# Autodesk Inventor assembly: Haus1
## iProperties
Shininess: 64.0
Length Units: 11269
Angle Units: 11279
Time Units: 11290
Mass Units: 11283
Length Display Precision: 3
Angle Display Precision: 2
Compacted: True
Created: 2003-12
Part Number: Haus1
Document SubType Name: Assembly
Designer: HAH
Manufacturer: Standard
Standards Organization: Custom
Density: 0.0
Volumn: 0.0
Area: 0.0
PropertySet Name: Model Information
Control State: 0
Master: False
Checked Out: False
Author: HAH
